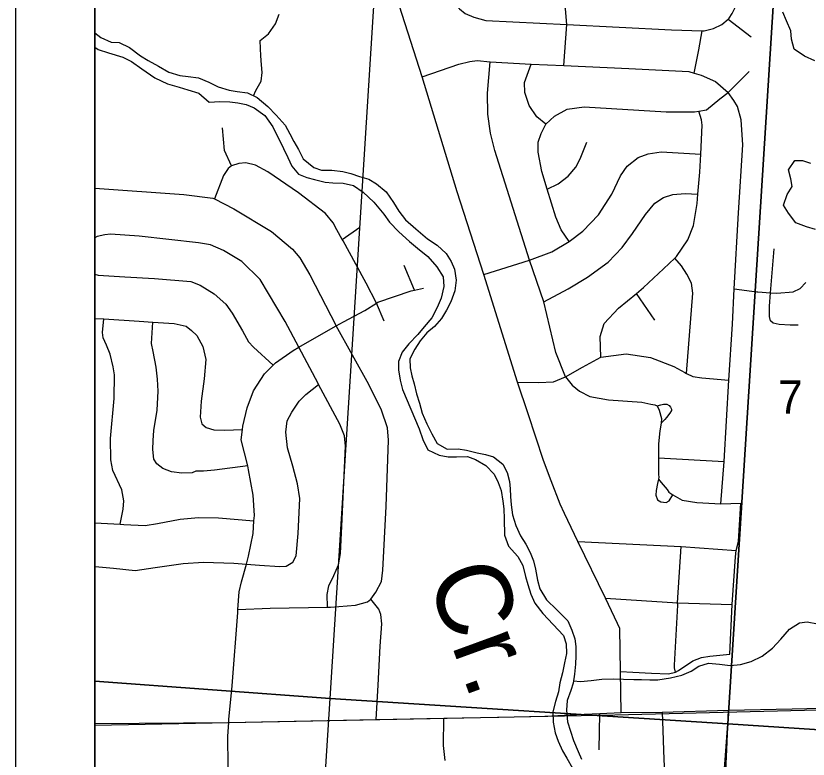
# Model space of a CAD drawing. Extents: x 0 to 34, y 0 to 26.1.
# Drawn here: x 23.417 to 24.419, y 19.216 to 20.156 of the extents above; entities that cross this region are included whole.
import ezdxf

# ---------------------------------------------------------------- set-up
doc = ezdxf.new("R2010")
doc.units = 0
for name, color, linetype in [('GM_X_City_Street', 7, 'Continuous'), ('GM_X_County_Road', 7, 'Continuous'), ('GM_X_Minor_River', 7, 'Continuous'), ('GM_X_Minor_River_Text', 7, 'Continuous'), ('GM_X_Rail_Line', 7, 'Continuous'), ('GM_X_Section', 7, 'Continuous'), ('GM_X_Section_Text', 7, 'Continuous'), ('GM_X_State_Route', 7, 'Continuous'), ('GM_X_US_Route', 7, 'Continuous'), ('SC_Scratch1', 7, 'Continuous'), ('SH_Data', 7, 'Continuous')]:
    doc.layers.add(name, color=color, linetype=linetype)

msp = doc.modelspace()

# ---------------------------------------------------------------- linework, layer by layer
at = {"layer": 'GM_X_City_Street'}
for p, q in [((24.3178, 20.1515), (24.3469, 20.1292)), ((24.3176, 20.0586), (24.3443, 20.0852)), ((23.8296, 19.8728), (23.8519, 19.8883)), ((24.3713, 19.8055), (24.376, 19.8612)), ((23.9211, 19.8089), (23.9078, 19.8398)), ((24.2249, 19.7708), (24.2016, 19.8045)), ((23.8827, 19.7694), (23.873, 19.7925)), ((24.2296, 19.5967), (24.3125, 19.5923)), ((24.1547, 19.2276), (24.1554, 19.2734)), ((24.3158, 19.2282), (24.318, 19.2779)), ((24.3141, 19.1885), (24.3158, 19.2282))]:
    msp.add_line(p, q, dxfattribs=at)
for points in [[(24.1097, 20.0927), (24.1138, 20.1445), (24.1121, 20.1645), (24.1089, 20.1743), (24.1052, 20.1817), (24.0962, 20.1931), (24.0811, 20.2086), (24.0725, 20.2217), (24.0664, 20.2344), (24.0627, 20.2478), (24.0603, 20.2605), (24.0599, 20.2748), (24.0619, 20.3111), (24.0672, 20.3973)], [(23.9602, 20.214), (23.9602, 20.1972), (23.9647, 20.1825), (23.9704, 20.1719), (23.9778, 20.1645), (23.9851, 20.1584), (23.9959, 20.1539), (24.0113, 20.1498), (24.1138, 20.1445), (24.2462, 20.1378), (24.2847, 20.1368), (24.2873, 20.1368), (24.2991, 20.1395), (24.3098, 20.1446), (24.3178, 20.1515), (24.3191, 20.1527), (24.3226, 20.1587), (24.329, 20.1714), (24.3302, 20.19)], [(24.2745, 20.0833), (24.2807, 20.1126), (24.2847, 20.1368)], [(23.9308, 20.0784), (23.977, 20.0943), (23.9908, 20.098), (24.0002, 20.0992), (24.0166, 20.0976), (24.0684, 20.0947), (24.1097, 20.0927), (24.1921, 20.089), (24.268, 20.0852), (24.2745, 20.0833), (24.2834, 20.0807), (24.3017, 20.0726), (24.3176, 20.0586)], [(24.1119, 19.6993), (24.0999, 19.7298), (24.0844, 19.7942), (24.0664, 19.8468), (24.0227, 19.9853), (24.017, 20.0073), (24.0137, 20.0314), (24.0133, 20.058), (24.0166, 20.0976)], [(24.0872, 20.0187), (24.0757, 20.0278), (24.0658, 20.0421), (24.0605, 20.0585), (24.0601, 20.0714), (24.0684, 20.0947)], [(24.0872, 20.0187), (24.098, 20.0287), (24.1141, 20.0374), (24.1357, 20.0407), (24.2391, 20.0343), (24.2751, 20.0342), (24.2807, 20.0352), (24.2902, 20.0368), (24.3072, 20.0505), (24.3176, 20.0586)], [(24.3085, 19.5386), (24.3125, 19.5923), (24.3187, 19.6951), (24.323, 19.7657), (24.3254, 19.8104), (24.3306, 19.9064), (24.3361, 19.9924), (24.3342, 20.024), (24.3293, 20.0408), (24.3249, 20.0485), (24.3176, 20.0586)], [(24.1568, 19.7239), (24.1559, 19.7501), (24.1609, 19.7667), (24.1791, 19.7859), (24.2016, 19.8045), (24.2107, 19.8121), (24.2359, 19.8358), (24.2502, 19.8491), (24.2525, 19.8513), (24.2666, 19.8722), (24.2739, 19.8907), (24.2783, 19.9183), (24.2794, 19.9301), (24.2819, 19.9581), (24.283, 19.9808), (24.2848, 20.0172), (24.2839, 20.0241), (24.2807, 20.0352)], [(23.6896, 19.9661), (23.6807, 19.9852), (23.678, 20.0141)], [(24.1166, 19.8701), (24.1063, 19.885), (24.0998, 19.9011), (24.0889, 19.9365), (24.0819, 19.9589), (24.0772, 19.9833), (24.0775, 19.9958), (24.0812, 20.0067), (24.0872, 20.0187)], [(24.0889, 19.9365), (24.1027, 19.9432), (24.1151, 19.9531), (24.1248, 19.9643), (24.1303, 19.9748), (24.1388, 19.9958)], [(24.0088, 19.8285), (24.0664, 19.8468), (24.0946, 19.8571), (24.1166, 19.8701), (24.1338, 19.8832), (24.1538, 19.904), (24.1705, 19.9301), (24.1815, 19.9534), (24.1901, 19.9657), (24.204, 19.9763), (24.2167, 19.9812), (24.233, 19.9836), (24.283, 19.9808)], [(23.873, 19.7925), (23.8597, 19.8178), (23.8466, 19.8417), (23.8307, 19.871), (23.8296, 19.8728), (23.8227, 19.8852), (23.818, 19.8941), (23.8085, 19.9057), (23.7743, 19.932), (23.7352, 19.9584), (23.7196, 19.9668), (23.7075, 19.9697), (23.6988, 19.9688), (23.6896, 19.9661), (23.6851, 19.9627), (23.6792, 19.9537), (23.6681, 19.9241)], [(23.5167, 19.9376), (23.6291, 19.9299), (23.666, 19.9252), (23.6681, 19.9241), (23.6925, 19.9116), (23.7402, 19.8831), (23.7665, 19.8608), (23.7757, 19.8496), (23.7884, 19.828), (23.8217, 19.7635)], [(24.0844, 19.7942), (24.1154, 19.8103), (24.1396, 19.8253), (24.1661, 19.844), (24.1836, 19.8629), (24.1965, 19.8805), (24.213, 19.9043), (24.225, 19.9189), (24.2358, 19.9258), (24.2476, 19.9297), (24.2631, 19.9308), (24.2794, 19.9301)], [(23.8109, 19.408), (23.8105, 19.4241), (23.8127, 19.4351), (23.819, 19.4482), (23.8246, 19.4617), (23.8273, 19.4757), (23.8288, 19.5103), (23.8335, 19.6115), (23.8323, 19.6245), (23.8266, 19.6394), (23.7996, 19.6897), (23.7991, 19.6906), (23.7746, 19.7365), (23.7572, 19.7691), (23.7256, 19.8223), (23.7027, 19.8449), (23.6792, 19.8588), (23.6627, 19.866), (23.6476, 19.8687), (23.5726, 19.877), (23.5364, 19.8794), (23.5292, 19.8789), (23.5197, 19.8765), (23.5167, 19.8749)], [(24.2649, 19.7036), (24.273, 19.8049), (24.2714, 19.8175), (24.2656, 19.829), (24.2587, 19.8394), (24.2502, 19.8491)], [(23.5167, 19.8288), (23.5208, 19.8278), (23.5544, 19.8258), (23.5921, 19.8234), (23.6382, 19.8199), (23.6498, 19.8151), (23.6676, 19.804), (23.6821, 19.7911), (23.6901, 19.7795), (23.7032, 19.7572), (23.7108, 19.7433), (23.7171, 19.7367), (23.742, 19.714)], [(24.3254, 19.8104), (24.3541, 19.8068), (24.355, 19.8066), (24.3713, 19.8055), (24.3792, 19.8049), (24.4, 19.8067), (24.4088, 19.811), (24.4158, 19.8184)], [(23.6857, 19.169), (23.6849, 19.245), (23.6859, 19.262), (23.6861, 19.2658), (23.6902, 19.3086), (23.6973, 19.4011), (23.6976, 19.4052), (23.6991, 19.4273), (23.702, 19.4401), (23.7083, 19.4624), (23.7111, 19.4726), (23.7167, 19.5013), (23.7179, 19.5171), (23.7184, 19.524), (23.7167, 19.5495), (23.7111, 19.5815), (23.7099, 19.5865), (23.7018, 19.6194), (23.7032, 19.6325), (23.7037, 19.6368), (23.7092, 19.6598), (23.7173, 19.6813), (23.731, 19.7029), (23.742, 19.714), (23.745, 19.717), (23.7676, 19.7324), (23.7746, 19.7365), (23.8033, 19.7532), (23.8217, 19.7635), (23.8313, 19.7688), (23.8581, 19.7829), (23.873, 19.7925), (23.8746, 19.7935), (23.9169, 19.8081), (23.9211, 19.8089), (23.9321, 19.8111)], [(24.4062, 19.7647), (24.396, 19.7646), (24.382, 19.7653), (24.3745, 19.767), (24.3712, 19.7698), (24.3698, 19.7755), (24.3701, 19.7884), (24.3713, 19.8055)], [(23.5167, 19.7731), (23.5281, 19.7724), (23.5727, 19.7696), (23.5901, 19.7684), (23.6168, 19.7666), (23.6319, 19.7631), (23.6389, 19.7577), (23.6456, 19.7514), (23.6532, 19.7375), (23.657, 19.7211), (23.6549, 19.6965), (23.6512, 19.6685), (23.6499, 19.648), (23.652, 19.6396), (23.6572, 19.6353), (23.6669, 19.632), (23.6805, 19.6317), (23.7032, 19.6325)], [(23.5487, 19.5128), (23.5526, 19.532), (23.5532, 19.5426), (23.5506, 19.5563), (23.5394, 19.5809), (23.5367, 19.5942), (23.5366, 19.6212), (23.5412, 19.6716), (23.5416, 19.7016), (23.5399, 19.7119), (23.5361, 19.7279), (23.5315, 19.7391), (23.5272, 19.7487), (23.5262, 19.7551), (23.5281, 19.7724)], [(23.7099, 19.5865), (23.668, 19.5811), (23.6539, 19.5799), (23.6445, 19.5798), (23.6395, 19.578), (23.6267, 19.5776), (23.6135, 19.579), (23.6026, 19.5835), (23.5952, 19.589), (23.5912, 19.5952), (23.59, 19.6074), (23.5902, 19.6187), (23.5913, 19.6312), (23.5953, 19.657), (23.5966, 19.6809), (23.5959, 19.6964), (23.5943, 19.7113), (23.5903, 19.7311), (23.5883, 19.7414), (23.5901, 19.7684)], [(23.8656, 19.4182), (23.8722, 19.4268), (23.879, 19.4406), (23.8808, 19.4547), (23.885, 19.5351), (23.8882, 19.6193), (23.8866, 19.6345), (23.8792, 19.6571), (23.863, 19.6894), (23.8217, 19.7635)], [(24.0513, 19.6925), (24.0778, 19.692), (24.0967, 19.6927), (24.1119, 19.6993), (24.1335, 19.7115), (24.1568, 19.7239), (24.1887, 19.7284), (24.2196, 19.7238), (24.2488, 19.7121), (24.263, 19.7045), (24.2649, 19.7036), (24.2731, 19.6997), (24.2844, 19.6979), (24.3187, 19.6951)], [(24.1119, 19.6993), (24.1204, 19.6887), (24.1297, 19.6812), (24.1428, 19.6744), (24.1665, 19.6701), (24.2084, 19.6671), (24.22, 19.6648), (24.2248, 19.6636), (24.2278, 19.6626), (24.2324, 19.6639), (24.2358, 19.6646), (24.2377, 19.6648), (24.24, 19.6646), (24.243, 19.663), (24.2449, 19.6609), (24.2459, 19.6583), (24.246, 19.6567), (24.244, 19.6533), (24.2398, 19.6476), (24.2374, 19.6451), (24.2331, 19.6407)], [(23.5167, 19.4594), (23.5172, 19.4592), (23.5402, 19.4574), (23.5674, 19.4545), (23.5928, 19.458), (23.6285, 19.4632), (23.6542, 19.4649), (23.6924, 19.4635), (23.7083, 19.4624), (23.7248, 19.4612), (23.7505, 19.4594), (23.7584, 19.46), (23.7669, 19.4647), (23.7712, 19.473), (23.7738, 19.501), (23.776, 19.5454), (23.773, 19.5637), (23.7671, 19.5862), (23.7601, 19.6096), (23.758, 19.6294), (23.7598, 19.6434), (23.7658, 19.6546), (23.7752, 19.6684), (23.7833, 19.677), (23.7996, 19.6897)], [(24.2278, 19.6626), (24.2302, 19.657), (24.2332, 19.6465), (24.2331, 19.6407), (24.2313, 19.6309), (24.2294, 19.6146), (24.2296, 19.5967), (24.2296, 19.5906), (24.2296, 19.5755), (24.2299, 19.5724), (24.2294, 19.5698), (24.2282, 19.5645), (24.2265, 19.5554), (24.2264, 19.5497), (24.2285, 19.5436), (24.2326, 19.5412), (24.2394, 19.5403), (24.2432, 19.5425), (24.2479, 19.5499)], [(24.2294, 19.5698), (24.2328, 19.5655), (24.2405, 19.5566), (24.2427, 19.5535), (24.2479, 19.5499), (24.2595, 19.5432), (24.2779, 19.5401), (24.3085, 19.5386), (24.3335, 19.5393)], [(24.3196, 19.3486), (24.3228, 19.4115), (24.3269, 19.4716), (24.3277, 19.4797), (24.3306, 19.4912), (24.3335, 19.5393)], [(23.5167, 19.5145), (23.5487, 19.5128), (23.5533, 19.5126), (23.5801, 19.5111), (23.596, 19.5138), (23.6245, 19.5192), (23.6476, 19.5212), (23.673, 19.521), (23.7179, 19.5171)], [(24.1276, 19.4908), (24.2583, 19.4846), (24.3277, 19.4797)], [(24.2509, 19.326), (24.2498, 19.3312), (24.2499, 19.3348), (24.2539, 19.4104), (24.2538, 19.4136), (24.2583, 19.4846)], [(23.6976, 19.4052), (23.7383, 19.4066), (23.8109, 19.408), (23.8147, 19.4081), (23.8465, 19.4103), (23.8613, 19.4149), (23.8656, 19.4182)], [(23.8725, 19.2659), (23.8751, 19.3094), (23.8777, 19.3587), (23.8796, 19.3867), (23.8783, 19.3985), (23.8758, 19.4054), (23.8656, 19.4182)], [(24.1624, 19.4193), (24.2538, 19.4136), (24.3228, 19.4115)], [(24.1817, 19.3266), (24.1971, 19.3259), (24.2206, 19.3246), (24.2421, 19.3235), (24.2509, 19.326), (24.2547, 19.328), (24.2731, 19.3401), (24.2838, 19.3444), (24.2944, 19.346), (24.3196, 19.3486)], [(23.9597, 19.2143), (23.9574, 19.2329), (23.958, 19.2676)]]:
    msp.add_lwpolyline(points, dxfattribs=at)
at = {"layer": 'GM_X_County_Road'}
msp.add_line((24.1823, 19.2746), (24.1817, 19.3266), dxfattribs=at)
for points in [[(24.1107, 19.5265), (24.1052, 19.5381), (24.0938, 19.5679), (24.084, 19.5932), (24.0648, 19.6525), (24.0513, 19.6925), (24.0088, 19.8285), (23.9749, 19.933), (23.9308, 20.0784), (23.8908, 20.2025), (23.8251, 20.412), (23.7846, 20.5451), (23.7171, 20.7636), (23.6963, 20.8299)], [(24.1817, 19.3266), (24.1807, 19.3809), (24.1778, 19.3875), (24.1624, 19.4193), (24.1276, 19.4908), (24.1107, 19.5265)]]:
    msp.add_lwpolyline(points, dxfattribs=at)
at = {"layer": 'GM_X_Minor_River'}
for points in [[(23.7172, 20.0545), (23.7204, 20.0611), (23.7269, 20.0728), (23.7281, 20.0838), (23.7274, 20.0937), (23.7267, 20.1051), (23.726, 20.1145), (23.7257, 20.1244), (23.7363, 20.1327), (23.7451, 20.1455), (23.7497, 20.1577)], [(24.4274, 20.0985), (24.4142, 20.1046), (24.401, 20.1134), (24.3977, 20.1263), (24.397, 20.1366), (24.3914, 20.1491), (24.3869, 20.1602)], [(23.5167, 20.1341), (23.5241, 20.1283), (23.5373, 20.1222), (23.5475, 20.1217), (23.5604, 20.1156), (23.5743, 20.1052), (23.5841, 20.0991), (23.5969, 20.0918), (23.6101, 20.0845), (23.624, 20.0803), (23.6346, 20.0791), (23.6479, 20.0771), (23.6607, 20.0717), (23.6727, 20.0659), (23.6867, 20.0617), (23.6965, 20.0601), (23.7098, 20.0581), (23.7218, 20.0523), (23.7354, 20.0409), (23.7459, 20.0302), (23.7575, 20.0172), (23.7631, 20.0065), (23.7684, 19.9966), (23.774, 19.9867), (23.78, 19.9746), (23.7935, 19.9639), (23.8033, 19.9604), (23.8162, 19.9603), (23.8302, 19.9587), (23.8404, 19.9564), (23.8513, 19.9525), (23.863, 19.949), (23.8728, 19.9432), (23.8852, 19.9329), (23.8942, 19.9196), (23.9009, 19.9085), (23.9096, 19.8975), (23.9227, 19.8864), (23.9374, 19.8738), (23.9498, 19.8657), (23.9611, 19.855), (23.9675, 19.8448), (23.9716, 19.8352), (23.9738, 19.8216), (23.9718, 19.8079), (23.9668, 19.7939), (23.9614, 19.7833), (23.9549, 19.7731), (23.9462, 19.7629), (23.9367, 19.755), (23.9283, 19.7448), (23.9214, 19.7342), (23.9149, 19.7221), (23.9156, 19.7107), (23.9174, 19.7005), (23.9204, 19.6902), (23.9234, 19.6777), (23.9271, 19.6659), (23.9308, 19.6533), (23.9367, 19.6396), (23.9427, 19.6271), (23.9498, 19.6149), (23.9622, 19.6076), (23.9762, 19.6083), (23.9868, 19.6063), (24, 19.6032), (24.0106, 19.6012), (24.0208, 19.5981), (24.0328, 19.5886), (24.0381, 19.5783), (24.041, 19.5669), (24.0421, 19.5574), (24.0424, 19.5479), (24.0431, 19.5373), (24.0449, 19.5247), (24.049, 19.5114), (24.055, 19.4981), (24.0617, 19.4878), (24.0673, 19.4772), (24.0714, 19.4665)], [(23.5167, 20.1161), (23.5206, 20.1132), (23.5338, 20.1089), (23.552, 20.1035), (23.5629, 20.0977), (23.5761, 20.0885), (23.5923, 20.0771), (23.6085, 20.0697), (23.6232, 20.0655), (23.6341, 20.062), (23.6481, 20.0577), (23.6613, 20.0466), (23.6745, 20.0473), (23.6874, 20.0469), (23.6976, 20.0457), (23.7082, 20.0433), (23.718, 20.0391), (23.7315, 20.0295), (23.7416, 20.0154), (23.7551, 19.988), (23.7607, 19.9766), (23.7659, 19.9655), (23.7742, 19.9556), (23.7847, 19.9514), (23.7946, 19.9487), (23.8078, 19.9452), (23.8176, 19.9443), (23.8308, 19.9439), (23.8437, 19.9412), (23.8561, 19.9327), (23.8696, 19.9201), (23.882, 19.9049), (23.8895, 19.8946), (23.9012, 19.8824), (23.9147, 19.8705), (23.9249, 19.8617), (23.9377, 19.8514), (23.9493, 19.8384), (23.9572, 19.8255), (23.9582, 19.8133), (23.9547, 19.7985), (23.9494, 19.7868), (23.9429, 19.7739), (23.933, 19.7626), (23.9253, 19.7528), (23.9139, 19.7411), (23.9055, 19.7305), (23.9005, 19.7184), (23.9005, 19.7082), (23.9027, 19.6949), (23.9052, 19.685), (23.9058, 19.683)], [(24.428, 19.8856), (24.4167, 19.8887), (24.4034, 19.8937), (24.3941, 19.9063), (24.3877, 19.9162), (24.3923, 19.9298), (24.3988, 19.94), (24.397, 19.9495), (24.394, 19.9609), (24.402, 19.9726), (24.4119, 19.9726), (24.4217, 19.9695)], [(23.9058, 19.683), (23.9269, 19.6336), (23.9313, 19.6199), (23.938, 19.607), (23.952, 19.6001), (23.9633, 19.5981), (23.9739, 19.598), (23.9879, 19.5983), (23.9981, 19.5945), (24.0113, 19.5872), (24.0218, 19.5761), (24.0267, 19.5655), (24.0304, 19.5556), (24.0326, 19.5419), (24.034, 19.5324), (24.0343, 19.5195), (24.0349, 19.499), (24.0398, 19.4853), (24.0518, 19.4719), (24.0578, 19.4605), (24.0615, 19.4468), (24.0644, 19.4366), (24.0681, 19.4244), (24.073, 19.413), (24.0831, 19.4), (24.0963, 19.3859), (24.1094, 19.3722), (24.1128, 19.3615), (24.1131, 19.3494), (24.1107, 19.3376), (24.108, 19.3251), (24.1049, 19.3122), (24.1029, 19.3008), (24.0991, 19.2887), (24.096, 19.2755), (24.0963, 19.2626), (24.0988, 19.2493), (24.1025, 19.2386), (24.1081, 19.2264), (24.1138, 19.2169), (24.1209, 19.2043)], [(24.0714, 19.4665), (24.074, 19.4562), (24.0766, 19.4422), (24.0795, 19.4312), (24.0881, 19.4174), (24.1009, 19.4045), (24.1148, 19.3907), (24.12, 19.3789), (24.1238, 19.3679), (24.1252, 19.3584), (24.1251, 19.3463), (24.1247, 19.336), (24.1235, 19.3231), (24.1215, 19.3121), (24.1188, 19.3026), (24.1142, 19.2898), (24.113, 19.2776), (24.1144, 19.2628), (24.1181, 19.251), (24.1222, 19.2392), (24.1278, 19.2255), (24.1323, 19.2157)], [(24.122, 19.315), (24.131, 19.314), (24.1446, 19.3154), (24.1579, 19.3168), (24.1722, 19.3175), (24.1851, 19.317), (24.1983, 19.3166), (24.2082, 19.3165), (24.2187, 19.3161), (24.2286, 19.316), (24.2449, 19.3186), (24.2592, 19.3219), (24.271, 19.3271), (24.2805, 19.3332), (24.2926, 19.3373), (24.3066, 19.336), (24.3202, 19.3344), (24.3331, 19.3355), (24.3467, 19.3392), (24.3607, 19.3459), (24.3737, 19.3561), (24.3843, 19.3674), (24.3954, 19.3803), (24.4079, 19.3882), (24.4177, 19.3896), (24.4306, 19.3869)]]:
    msp.add_lwpolyline(points, dxfattribs=at)
at = {"layer": 'GM_X_Rail_Line'}
msp.add_lwpolyline([(23.5167, 19.2589), (24.1745, 19.2718), (25.3226, 19.2999)], dxfattribs=at)
at = {"layer": 'GM_X_Section'}
for points in [[(23.5167, 20.3181), (23.5167, 19.3144), (23.8141, 19.2924), (23.8774, 20.2949)], [(23.8774, 20.2949), (24.3803, 20.2612), (24.3172, 19.2604), (23.8141, 19.2924)], [(24.3803, 20.2612), (24.8799, 20.2275), (24.8136, 19.2279), (24.3172, 19.2604)], [(23.5167, 19.3144), (23.5167, 18.3211), (23.7513, 18.3069), (23.8141, 19.2924)], [(23.8141, 19.2924), (24.3172, 19.2604), (24.2441, 18.2726), (23.7513, 18.3069)], [(24.3172, 19.2604), (24.8136, 19.2279), (24.7496, 18.2359), (24.2441, 18.2726)]]:
    msp.add_lwpolyline(points, close=True, dxfattribs=at)
at = {"layer": 'GM_X_State_Route'}
for points in [[(24.2344, 19.2754), (24.2353, 19.2404), (24.2358, 19.2265)], [(24.2358, 19.2265), (24.2374, 19.1868), (24.2389, 19.144), (24.2398, 19.1185), (24.241, 19.1117), (24.2443, 19.1056), (24.2464, 19.1032)]]:
    msp.add_lwpolyline(points, dxfattribs=at)
at = {"layer": 'GM_X_US_Route'}
msp.add_line((24.0866, 19.2702), (24.1259, 19.2721), dxfattribs=at)
for points in [[(24.1259, 19.2721), (24.1554, 19.2734), (24.1823, 19.2746), (24.2344, 19.2754), (24.318, 19.2779), (24.3987, 19.2796), (24.5833, 19.2837), (24.6675, 19.2858), (24.7192, 19.2879)], [(23.5167, 19.2611), (23.6847, 19.262), (23.6859, 19.262), (23.8725, 19.2659), (23.958, 19.2676), (24.0274, 19.269), (24.0857, 19.2702), (24.0866, 19.2702)]]:
    msp.add_lwpolyline(points, dxfattribs=at)
at = {"layer": 'SC_Scratch1'}
msp.add_lwpolyline([(23.5167, 20.8446), (23.5167, 17.6974)], dxfattribs=at)
at = {"layer": 'SH_Data'}
for points in [[(23.4167, 21), (30.4167, 21), (30.4167, 14), (23.4167, 14)], [(23.5167, 20.9), (30.3167, 20.9), (30.3167, 14.1), (23.5167, 14.1)]]:
    msp.add_lwpolyline(points, close=True, dxfattribs=at)

# ---------------------------------------------------------------- texts
at = {"layer": 'GM_X_Minor_River_Text'}
msp.add_text('Cr.', height=0.0947, rotation=289.9992, dxfattribs=at).set_placement((23.936, 19.4468))
at = {"layer": 'GM_X_Section_Text'}
msp.add_text('7', height=0.0419, rotation=0, dxfattribs=at).set_placement((24.3808, 19.6527))

doc.saveas('drawing.dxf')
